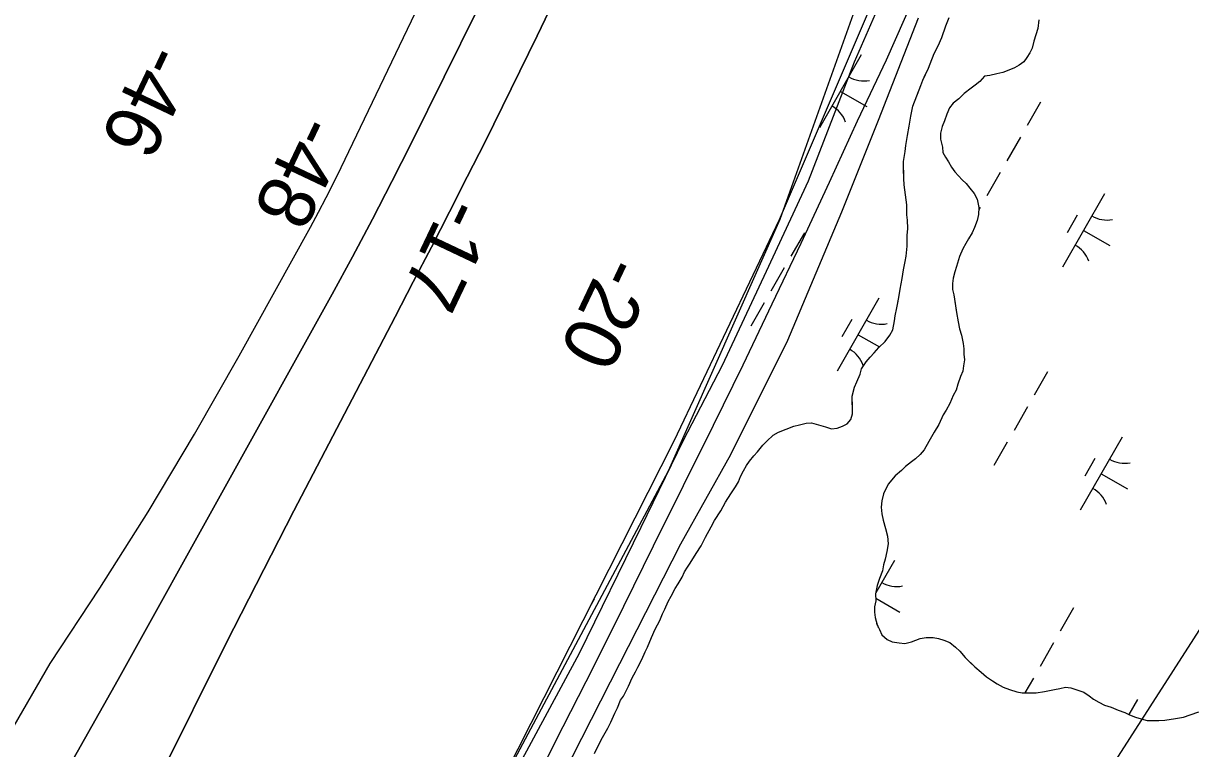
# Model space of a CAD drawing. Extents: x 3930721 to 3950824, y 220441 to 242861.
# Drawn here: x 3941033 to 3941726, y 228826 to 229257 of the extents above; entities that cross this region are included whole.
import ezdxf

# ---------------------------------------------------------------- set-up
doc = ezdxf.new("R2010")
doc.units = 0
for name, color, linetype in [('V-RIVR-EDGE', 7, 'Continuous'), ('V-RIVR-JETY', 7, 'Continuous'), ('V-RIVR-RANG', 7, 'Continuous'), ('V-RRAP-FSHR', 7, 'Continuous'), ('V-TOPO-DPTH', 7, 'Continuous'), ('V-TOPO-MINR', 7, 'Continuous'), ('V-TOPO-SHOR', 7, 'Continuous'), ('V-UTIL-LINE', 7, 'Continuous'), ('V-WETL-SWMP', 7, 'Continuous')]:
    doc.layers.add(name, color=color, linetype=linetype)

msp = doc.modelspace()

# ---------------------------------------------------------------- linework, layer by layer
at = {"layer": 'V-RIVR-EDGE'}
msp.add_lwpolyline([(3941745.08, 229747.52), (3941575.06, 229419.28), (3941527.83, 229268.14), (3941482.17, 229140.62), (3941416.05, 228991.06), (3941301.1, 228775.92)], dxfattribs=at)
at = {"layer": 'V-RIVR-JETY'}
for points in [[(3941326.68, 228815.04), (3941363.35, 228883.05), (3941399.95, 228957.74), (3941424.99, 229009.51), (3941448.13, 229054.18), (3941474.31, 229109.89), (3941499.32, 229163.62), (3941526.53, 229234.29), (3941555.74, 229301.04)], [(3941564.41, 229260.23), (3941540.64, 229199.43), (3941518.78, 229144.94), (3941486.91, 229068.73), (3941453, 229000.75), (3941423.25, 228947.75), (3941387.01, 228876.6), (3941347.68, 228799.13)]]:
    msp.add_lwpolyline(points, dxfattribs=at)
at = {"layer": 'V-RRAP-FSHR'}
msp.add_lwpolyline([(3941335.66, 228803.74), (3941353.72, 228839.43), (3941371.78, 228875.12), (3941389.59, 228910.93), (3941407.35, 228946.78), (3941425.1, 228982.62), (3941442.85, 229018.46), (3941460.55, 229054.34), (3941477.72, 229090.46), (3941494.9, 229126.58), (3941511.79, 229162.84), (3941528.43, 229199.22), (3941545.57, 229235.6), (3941561.69, 229271.97)], dxfattribs=at)
at = {"layer": 'V-TOPO-DPTH'}
for points in [[(3941681.59, 229966.31), (3941338.17, 229249.76), (3941327.99, 229228.71), (3941317.7, 229207.72), (3941307.26, 229186.79), (3941296.72, 229165.92), (3941286.08, 229145.1), (3941275.39, 229124.3), (3941264.65, 229103.53), (3941253.87, 229082.78), (3941193.79, 228967.53), (3941153.58, 228888.86), (3941114.24, 228809.77), (3941076.18, 228730.04), (3941038.99, 228649.9), (3940868.17, 228273.87), (3940856.26, 228248.8), (3940843.8, 228224.03), (3940830.5, 228199.7), (3940816.64, 228175.66), (3940715.12, 228006.28)], [(3940564.46, 227999.47), (3940595.11, 228056.12), (3940624.65, 228113.35), (3940653.45, 228170.98), (3940707.26, 228281.31), (3940708.02, 228284), (3940708.19, 228286.63), (3941049.01, 228876.88), (3941078.54, 228921.67), (3941107.23, 228966.97), (3941134.67, 229013.05), (3941161.28, 229059.63), (3941203.6, 229136.16), (3941208.33, 229144.91), (3941212.97, 229153.71), (3941217.45, 229162.59), (3941221.82, 229171.53), (3941534.21, 229824.03)], [(3940564.46, 227999.47), (3940595.11, 228056.12), (3940624.65, 228113.35), (3940653.45, 228170.98), (3940707.26, 228281.31), (3940708.02, 228284), (3940708.19, 228286.63), (3941049.01, 228876.88), (3941078.54, 228921.67), (3941107.23, 228966.97), (3941134.67, 229013.05), (3941161.28, 229059.63), (3941203.6, 229136.16), (3941208.33, 229144.91), (3941212.97, 229153.71), (3941217.45, 229162.59), (3941221.82, 229171.53), (3941534.21, 229824.03)], [(3941033.83, 228768.68), (3941089.44, 228867.29), (3941216.43, 229096.36), (3941228.51, 229118.53), (3941240.39, 229140.81), (3941251.96, 229163.25), (3941263.32, 229185.81), (3941341.83, 229344.44), (3941392.01, 229446.53), (3941441.84, 229548.79), (3941491.13, 229651.31), (3941540.05, 229754)], [(3941540.05, 229754), (3941491.13, 229651.31), (3941441.84, 229548.79), (3941392.01, 229446.53), (3941341.83, 229344.44), (3941263.32, 229185.81), (3941251.96, 229163.25), (3941240.39, 229140.81), (3941228.51, 229118.53), (3941216.43, 229096.36), (3941089.44, 228867.29), (3941033.83, 228768.68)]]:
    msp.add_lwpolyline(points, dxfattribs=at)
at = {"layer": 'V-TOPO-MINR'}
for points in [[(3940715.12, 228006.28), (3940816.64, 228175.66), (3940830.5, 228199.7), (3940843.8, 228224.03), (3940856.26, 228248.8), (3940868.17, 228273.87), (3941038.99, 228649.9), (3941076.18, 228730.04), (3941114.24, 228809.77), (3941153.58, 228888.86), (3941193.79, 228967.53), (3941253.87, 229082.78), (3941264.65, 229103.53), (3941275.39, 229124.3), (3941286.08, 229145.1), (3941296.72, 229165.92), (3941307.26, 229186.79), (3941317.7, 229207.72), (3941327.99, 229228.71), (3941338.17, 229249.76), (3941681.59, 229966.31)], [(3940564.46, 227999.47), (3940595.11, 228056.12), (3940624.65, 228113.35), (3940653.45, 228170.98), (3940707.26, 228281.31), (3940708.02, 228284), (3940708.19, 228286.63), (3941049.01, 228876.88), (3941078.54, 228921.67), (3941107.23, 228966.97), (3941134.67, 229013.05), (3941161.28, 229059.63), (3941203.6, 229136.16), (3941208.33, 229144.91), (3941212.97, 229153.71), (3941217.45, 229162.59), (3941221.82, 229171.53), (3941534.21, 229824.03)], [(3941033.83, 228768.68), (3941089.44, 228867.29), (3941216.43, 229096.36), (3941228.51, 229118.53), (3941240.39, 229140.81), (3941251.96, 229163.25), (3941263.32, 229185.81), (3941341.83, 229344.44), (3941392.01, 229446.53), (3941441.84, 229548.79), (3941491.13, 229651.31), (3941540.05, 229754)]]:
    msp.add_lwpolyline(points, dxfattribs=at)
at = {"layer": 'V-TOPO-SHOR'}
for points in [[(3941432.55, 228942.15), (3941435.65, 228946.72), (3941438.05, 228951.99), (3941441.48, 228957.97), (3941443.54, 228961.83), (3941447.33, 228967.46), (3941450.07, 228972.73), (3941453.17, 228977.66), (3941455.92, 228981.88), (3941457.64, 228984.7), (3941459, 228987.85), (3941460.72, 228991.37), (3941462.43, 228994.53), (3941464.16, 228996.99), (3941466.92, 229000.17), (3941468.99, 229002.64), (3941472.1, 229006.51), (3941474.52, 229008.98), (3941478.33, 229012.52), (3941481.46, 229014.3), (3941485.98, 229016.09), (3941490.51, 229017.88), (3941494, 229018.62), (3941497.83, 229019.7), (3941500.98, 229019.74), (3941505.18, 229018.73), (3941509.39, 229017.38), (3941512.89, 229016.36), (3941516.38, 229016.75), (3941519.52, 229017.83), (3941522.3, 229019.25), (3941524.37, 229021.72), (3941525.39, 229025.23), (3941525.34, 229029.42), (3941525.28, 229035.71), (3941526.62, 229040.97), (3941527.99, 229044.13), (3941530.04, 229048.69), (3941530.71, 229051.84), (3941533.46, 229056.07), (3941535.88, 229058.89), (3941538.3, 229061.36), (3941541.07, 229064.53), (3941544.88, 229068.07), (3941547.63, 229071.94), (3941549.35, 229075.1), (3941550.34, 229080.35), (3941550.66, 229083.5), (3941551.66, 229088.06), (3941552.33, 229091.21), (3941553, 229094.36), (3941553.65, 229099.26), (3941554.98, 229105.57), (3941555.63, 229110.82), (3941556.62, 229115.72), (3941557.29, 229118.87), (3941557.93, 229124.82), (3941557.87, 229131.11), (3941558.18, 229135.31), (3941558.12, 229140.2), (3941557.74, 229143.34), (3941557.68, 229149.29), (3941556.92, 229155.22), (3941556.17, 229161.15), (3941555.78, 229164.99), (3941555.72, 229170.59), (3941555.68, 229175.13), (3941556.66, 229181.08), (3941556.98, 229184.58), (3941557.96, 229190.53), (3941558.96, 229196.13), (3941559.95, 229202.09), (3941561.28, 229208.04), (3941564.01, 229215.06), (3941566.05, 229220.32), (3941567.07, 229223.48), (3941568.78, 229226.99), (3941570.49, 229230.51), (3941572.54, 229235.77), (3941573.9, 229239.28), (3941576.3, 229243.85), (3941578.35, 229248.76), (3941580.72, 229255.77), (3941582.77, 229260.69)], [(3941636.01, 229259.31), (3941635.36, 229254.06), (3941634, 229249.85), (3941632.99, 229246.69), (3941631.98, 229242.49), (3941630.61, 229239.68), (3941628.89, 229236.87), (3941627.17, 229234.4), (3941624.4, 229232.28), (3941621.61, 229230.85), (3941618.13, 229229.42), (3941614.65, 229227.98), (3941611.16, 229227.25), (3941606.98, 229226.16), (3941603.84, 229225.78), (3941601.08, 229222.6), (3941598.3, 229220.48), (3941595.87, 229218.7), (3941591.71, 229215.52), (3941588.6, 229212.34), (3941585.12, 229209.86), (3941583.06, 229207.04), (3941581.35, 229203.18), (3941579.99, 229199.32), (3941578.63, 229195.81), (3941577.62, 229191.96), (3941577.65, 229188.46), (3941578.75, 229183.58), (3941579.13, 229180.44), (3941580.56, 229177.66), (3941582.33, 229174.88), (3941584.11, 229171.75), (3941586.24, 229168.98), (3941588.36, 229166.55), (3941590.48, 229164.12), (3941592.95, 229162.05), (3941595.07, 229159.28), (3941597.55, 229156.16), (3941599.34, 229152.68), (3941600.43, 229147.8), (3941600.13, 229143.6), (3941599.46, 229140.1), (3941597.76, 229135.89), (3941596.39, 229132.73), (3941594.33, 229129.21), (3941592.61, 229126.4), (3941590.9, 229123.24), (3941588.84, 229118.67), (3941587.16, 229112.71), (3941586.14, 229109.56), (3941585.13, 229105.7), (3941584.81, 229102.55), (3941584.85, 229099.06), (3941585.58, 229095.92), (3941586.33, 229090.68), (3941587.08, 229085.45), (3941588.19, 229079.87), (3941588.93, 229075.68), (3941590.02, 229071.84), (3941591.12, 229066.96), (3941591.5, 229063.82), (3941591.53, 229060.68), (3941591.91, 229057.18)], [(3941591.91, 229057.18), (3941591.25, 229053.68), (3941590.93, 229050.53), (3941589.57, 229047.38), (3941587.87, 229042.81), (3941586.85, 229039.31), (3941585.14, 229036.14), (3941583.09, 229031.23), (3941581.03, 229027.37), (3941579.31, 229024.55), (3941576.57, 229018.93), (3941573.82, 229014.36), (3941570.73, 229008.74), (3941567.99, 229003.81), (3941565.57, 229000.99), (3941562.8, 228998.52), (3941560.37, 228996.75), (3941556.9, 228993.92), (3941554.48, 228991.44), (3941550.67, 228988.26), (3941548.6, 228985.79), (3941546.52, 228983.33), (3941545.15, 228980.52), (3941543.78, 228977.71), (3941542.78, 228973.5), (3941542.47, 228969.65), (3941542.86, 228965.81), (3941543.6, 228961.98), (3941545.04, 228957.1), (3941546.14, 228952.56), (3941546.53, 228948.02), (3941545.88, 228943.47), (3941544.88, 228938.92), (3941543.86, 228935.41), (3941543.2, 228931.91), (3941541.5, 228927.35), (3941540.14, 228923.14), (3941539.14, 228918.24), (3941539.19, 228914.05), (3941538.52, 228910.54), (3941538.56, 228907.4), (3941538.94, 228904.25), (3941540.03, 228899.72), (3941541.46, 228896.94), (3941542.89, 228893.81), (3941546.06, 228891.05), (3941548.87, 228889.68), (3941553.07, 228889.02), (3941556.57, 228888.71), (3941560.4, 228889.79), (3941565.63, 228891.59), (3941569.12, 228892.33), (3941573.31, 228892.37), (3941576.46, 228891.7), (3941579.62, 228890.69), (3941583.13, 228889.32), (3941586.65, 228886.56), (3941589.12, 228884.14), (3941592.31, 228880.33), (3941594.78, 228877.91), (3941597.96, 228874.79), (3941601.83, 228871.69), (3941605, 228868.92), (3941608.52, 228866.51), (3941611.34, 228864.79), (3941614.85, 228862.73), (3941618.71, 228861.37), (3941622.92, 228860.02), (3941626.07, 228859.35), (3941630.62, 228859.4), (3941634.46, 228859.44), (3941639.35, 228860.18), (3941645.28, 228861.29), (3941648.42, 228862.02), (3941651.9, 228862.76), (3941655.05, 228862.44), (3941659.26, 228861.08), (3941662.77, 228859.72), (3941665.94, 228857.66), (3941668.41, 228855.58), (3941671.57, 228853.87), (3941675.08, 228852.15), (3941678.94, 228850.8), (3941683.15, 228849.09), (3941687.01, 228847.73), (3941689.82, 228846.36), (3941693.33, 228845), (3941696.83, 228843.99), (3941700.34, 228842.98), (3941703.48, 228843.01), (3941707.33, 228843.05), (3941710.82, 228843.08), (3941717.1, 228844.19), (3941721.99, 228844.94), (3941725.82, 228846.38), (3941731.04, 228848.18)], [(3941372.24, 228823.4), (3941374.29, 228827.61), (3941377.04, 228832.88), (3941380.13, 228838.51), (3941381.84, 228842.02), (3941384.23, 228847.29), (3941385.95, 228850.45), (3941387.65, 228855.01), (3941389.37, 228857.48), (3941390.74, 228860.29), (3941392.46, 228863.45), (3941394.5, 228868.36), (3941396.57, 228871.88), (3941397.94, 228874.69), (3941400.34, 228879.26), (3941402.39, 228883.82), (3941403.76, 228886.63), (3941406.14, 228892.25), (3941408.19, 228897.16), (3941410.94, 228902.43), (3941412.64, 228906.3), (3941414.02, 228909.11), (3941416.06, 228913.67), (3941417.78, 228916.83), (3941420.18, 228921.4), (3941421.9, 228924.22), (3941424.31, 228928.08), (3941425.67, 228931.24), (3941427.39, 228934.06), (3941429.12, 228936.52), (3941432.55, 228942.15)]]:
    msp.add_lwpolyline(points, dxfattribs=at)
at = {"layer": 'V-UTIL-LINE'}
msp.add_lwpolyline([(3947453.78, 235874.4), (3945931.14, 235655.08), (3945509.06, 234777.68), (3940428.61, 226869.1), (3939084.62, 223621.72)], dxfattribs=at)
at = {"layer": 'V-WETL-SWMP'}
for p, q in [((3941530.63, 229238.46), (3941505.78, 229195.08)), ((3941518.2, 229216.77), (3941533.82, 229207.82)), ((3941637, 229210.3), (3941629.05, 229196.41)), ((3941625.07, 229189.47), (3941617.12, 229175.59)), ((3941613.14, 229168.64), (3941605.19, 229154.76)), ((3941674.97, 229155.8), (3941650.12, 229112.41)), ((3941601.21, 229147.82), (3941600.32, 229146.26)), ((3941658.83, 229143.14), (3941652.87, 229132.73)), ((3941496.83, 229132.75), (3941488.88, 229118.86)), ((3941662.54, 229134.1), (3941678.16, 229125.16)), ((3941484.91, 229111.92), (3941476.96, 229098.04)), ((3941472.98, 229091.09), (3941465.03, 229077.21)), ((3941541.1, 229093.91), (3941516.25, 229050.52)), ((3941524.96, 229081.25), (3941519, 229070.84)), ((3941528.68, 229072.21), (3941541.46, 229064.89)), ((3941641.18, 229050.08), (3941633.22, 229036.2)), ((3941629.25, 229029.25), (3941621.3, 229015.37)), ((3941617.32, 229008.43), (3941609.37, 228994.54)), ((3941685.44, 229011.24), (3941660.59, 228967.85)), ((3941669.31, 228998.59), (3941663.34, 228988.17)), ((3941673.02, 228989.55), (3941688.64, 228980.6)), ((3941550.25, 228938.03), (3941539.27, 228918.86)), ((3941372.12, 228914.98), (3941369.5, 228910.41)), ((3941539.17, 228915.56), (3941553.45, 228907.39)), ((3941656.62, 228909.86), (3941648.67, 228895.98)), ((3941644.69, 228889.04), (3941636.74, 228875.15)), ((3941632.77, 228868.21), (3941627.7, 228859.37)), ((3941694.59, 228855.36), (3941689.52, 228846.51))]:
    msp.add_line(p, q, dxfattribs=at)
for points in [[(3941759.88, 229782.48), (3941694.26, 229632.9), (3941629.26, 229484.54), (3941548.34, 229295.89), (3941481.78, 229140.52), (3941419.41, 229008.99), (3941326.77, 228826), (3941257.89, 228692.08), (3941204.73, 228595.87), (3941153.2, 228500.39), (3941067.67, 228329.19), (3941021.76, 228230.96), (3940968.37, 228111.89), (3940899.56, 227971.9)], [(3941410.94, 228902.43), (3941412.64, 228906.3), (3941414.01, 228909.11), (3941416.06, 228913.67), (3941417.78, 228916.83), (3941420.18, 228921.4), (3941421.9, 228924.21), (3941424.31, 228928.08), (3941425.67, 228931.24), (3941427.39, 228934.06), (3941429.12, 228936.52), (3941432.55, 228942.15), (3941435.65, 228946.72), (3941438.05, 228951.99), (3941441.48, 228957.97), (3941443.54, 228961.83), (3941447.33, 228967.46), (3941450.07, 228972.73), (3941453.17, 228977.66), (3941455.92, 228981.88), (3941457.64, 228984.7), (3941459, 228987.85), (3941460.72, 228991.37), (3941462.43, 228994.53), (3941464.16, 228996.99), (3941466.92, 229000.17), (3941468.99, 229002.64), (3941472.1, 229006.51), (3941474.52, 229008.98), (3941478.33, 229012.52), (3941481.46, 229014.3), (3941490.51, 229017.88), (3941494, 229018.62), (3941497.83, 229019.7), (3941500.97, 229019.74), (3941505.18, 229018.73), (3941509.39, 229017.38), (3941512.89, 229016.36), (3941516.38, 229016.75), (3941519.52, 229017.83), (3941522.3, 229019.25), (3941524.37, 229021.72), (3941525.39, 229025.23), (3941525.28, 229035.71), (3941526.62, 229040.97), (3941527.99, 229044.13), (3941530.04, 229048.69), (3941530.71, 229051.84), (3941533.46, 229056.07), (3941535.88, 229058.89), (3941538.3, 229061.36), (3941541.07, 229064.53), (3941544.88, 229068.07), (3941547.63, 229071.94), (3941549.35, 229075.1), (3941550.34, 229080.35), (3941550.66, 229083.5), (3941551.66, 229088.06), (3941553, 229094.36), (3941553.65, 229099.26), (3941554.98, 229105.57), (3941555.63, 229110.82), (3941556.63, 229115.72), (3941557.29, 229118.87), (3941557.93, 229124.82), (3941557.87, 229131.11), (3941558.18, 229135.31), (3941558.12, 229140.2), (3941557.74, 229143.34), (3941557.68, 229149.29), (3941556.17, 229161.15), (3941555.78, 229164.99), (3941555.68, 229175.13), (3941556.66, 229181.08), (3941556.98, 229184.58), (3941557.96, 229190.53), (3941558.96, 229196.13), (3941559.95, 229202.09), (3941561.28, 229208.04), (3941566.05, 229220.32), (3941567.07, 229223.48), (3941570.49, 229230.5), (3941573.9, 229239.28), (3941576.3, 229243.85), (3941578.35, 229248.76), (3941580.72, 229255.77), (3941582.77, 229260.69)], [(3941636.01, 229259.31), (3941635.36, 229254.06), (3941632.99, 229246.69), (3941631.98, 229242.49), (3941630.61, 229239.68), (3941628.89, 229236.86), (3941627.17, 229234.4), (3941624.4, 229232.28), (3941621.61, 229230.85), (3941614.65, 229227.98), (3941611.16, 229227.25), (3941606.98, 229226.16), (3941603.84, 229225.78), (3941601.08, 229222.6), (3941598.3, 229220.48), (3941595.87, 229218.71), (3941591.71, 229215.52), (3941588.6, 229212.34), (3941585.13, 229209.86), (3941583.06, 229207.04), (3941581.35, 229203.18), (3941579.99, 229199.32), (3941578.63, 229195.81), (3941577.62, 229191.96), (3941577.65, 229188.46), (3941578.75, 229183.58)], [(3941578.75, 229183.58), (3941579.13, 229180.44), (3941580.56, 229177.65), (3941582.33, 229174.88), (3941584.11, 229171.75), (3941586.24, 229168.98), (3941590.48, 229164.12), (3941592.95, 229162.05), (3941595.08, 229159.28), (3941597.55, 229156.16), (3941599.34, 229152.68), (3941600.43, 229147.8), (3941600.13, 229143.6), (3941599.46, 229140.1), (3941597.76, 229135.89), (3941596.39, 229132.73), (3941594.33, 229129.21), (3941592.61, 229126.4), (3941590.9, 229123.23), (3941588.85, 229118.67), (3941587.16, 229112.71), (3941586.14, 229109.55), (3941585.13, 229105.7), (3941584.81, 229102.55), (3941584.85, 229099.06), (3941585.58, 229095.92), (3941587.08, 229085.45), (3941588.19, 229079.87), (3941588.93, 229075.68), (3941590.02, 229071.85), (3941591.12, 229066.96), (3941591.5, 229063.82), (3941591.53, 229060.68), (3941591.91, 229057.18), (3941591.25, 229053.68), (3941590.93, 229050.53), (3941589.57, 229047.37), (3941587.87, 229042.81), (3941586.85, 229039.31), (3941585.14, 229036.14), (3941583.09, 229031.23), (3941581.03, 229027.36), (3941579.31, 229024.55), (3941576.57, 229018.93), (3941573.82, 229014.36), (3941570.73, 229008.74), (3941567.99, 229003.81), (3941565.57, 229000.99), (3941562.8, 228998.52), (3941560.37, 228996.75), (3941556.9, 228993.92), (3941554.48, 228991.44), (3941550.67, 228988.26), (3941546.52, 228983.33), (3941543.79, 228977.71), (3941542.78, 228973.5), (3941542.47, 228969.65), (3941542.86, 228965.81), (3941543.6, 228961.97), (3941545.04, 228957.1), (3941546.14, 228952.56), (3941546.53, 228948.02), (3941545.88, 228943.47), (3941544.88, 228938.92), (3941543.86, 228935.41), (3941543.2, 228931.91), (3941541.5, 228927.35), (3941540.14, 228923.14), (3941539.14, 228918.24), (3941539.19, 228914.05), (3941538.52, 228910.54), (3941538.56, 228907.4), (3941538.94, 228904.26), (3941540.03, 228899.72), (3941541.46, 228896.94), (3941542.89, 228893.81), (3941546.06, 228891.05), (3941548.87, 228889.68), (3941553.07, 228889.02), (3941556.57, 228888.71), (3941560.4, 228889.79), (3941565.63, 228891.59), (3941569.12, 228892.33), (3941573.31, 228892.37), (3941576.46, 228891.7), (3941579.62, 228890.69), (3941583.13, 228889.32), (3941586.65, 228886.56), (3941589.12, 228884.14), (3941592.31, 228880.33), (3941597.96, 228874.79), (3941601.83, 228871.69), (3941605, 228868.92), (3941608.52, 228866.51), (3941611.34, 228864.79), (3941614.85, 228862.73), (3941618.71, 228861.37), (3941622.92, 228860.02), (3941626.07, 228859.35), (3941634.46, 228859.43), (3941639.35, 228860.18)], [(3941372.24, 228823.4), (3941374.29, 228827.61), (3941377.04, 228832.88), (3941380.13, 228838.51), (3941381.84, 228842.02), (3941384.23, 228847.29), (3941385.95, 228850.45), (3941387.65, 228855.01), (3941389.37, 228857.48), (3941390.74, 228860.29), (3941392.46, 228863.45), (3941394.5, 228868.36), (3941396.56, 228871.88), (3941397.94, 228874.69), (3941400.33, 228879.26), (3941402.39, 228883.82), (3941403.76, 228886.63), (3941406.15, 228892.25), (3941408.19, 228897.16), (3941410.94, 228902.43)], [(3941639.35, 228860.18), (3941645.28, 228861.29), (3941648.42, 228862.02), (3941651.9, 228862.76), (3941655.05, 228862.44), (3941659.26, 228861.08), (3941662.77, 228859.72), (3941665.94, 228857.66), (3941668.4, 228855.58), (3941671.57, 228853.87), (3941675.08, 228852.16), (3941678.94, 228850.8), (3941683.15, 228849.09), (3941687.01, 228847.73), (3941689.82, 228846.36), (3941693.33, 228845), (3941700.34, 228842.98), (3941710.82, 228843.08), (3941717.1, 228844.19), (3941721.99, 228844.94), (3941725.82, 228846.38), (3941731.04, 228848.18)]]:
    msp.add_lwpolyline(points, dxfattribs=at)
for centre, start, end in [((3941532.14, 229240.62), 239.42788, 280.97154), ((3941504.68, 229192.68), 19.42788, 60.97154), ((3941676.48, 229157.95), 239.42788, 280.97154), ((3941649.02, 229110.02), 19.42788, 60.97154), ((3941542.61, 229096.06), 239.42788, 280.97154), ((3941515.16, 229048.12), 19.42788, 60.97154), ((3941686.95, 229013.4), 239.42788, 280.97154), ((3941659.5, 228965.46), 19.42788, 60.97154), ((3941551.76, 228940.19), 239.42788, 280.97154), ((3941524.3, 228892.25), 19.42788, 28.3308)]:
    msp.add_arc(centre, 17.62, start, end, dxfattribs=at)

# ---------------------------------------------------------------- texts
at = {"layer": 'V-RIVR-RANG'}
for s, p in [('-46', (3941106.39, 229247.25)), ('-48', (3941196.97, 229204.87)), ('-17', (3941284.39, 229155.83)), ('-20', (3941378.64, 229121.2))]:
    msp.add_text(s, height=33.5, rotation=244.63833, dxfattribs=at).set_placement(p)

doc.saveas('drawing.dxf')
